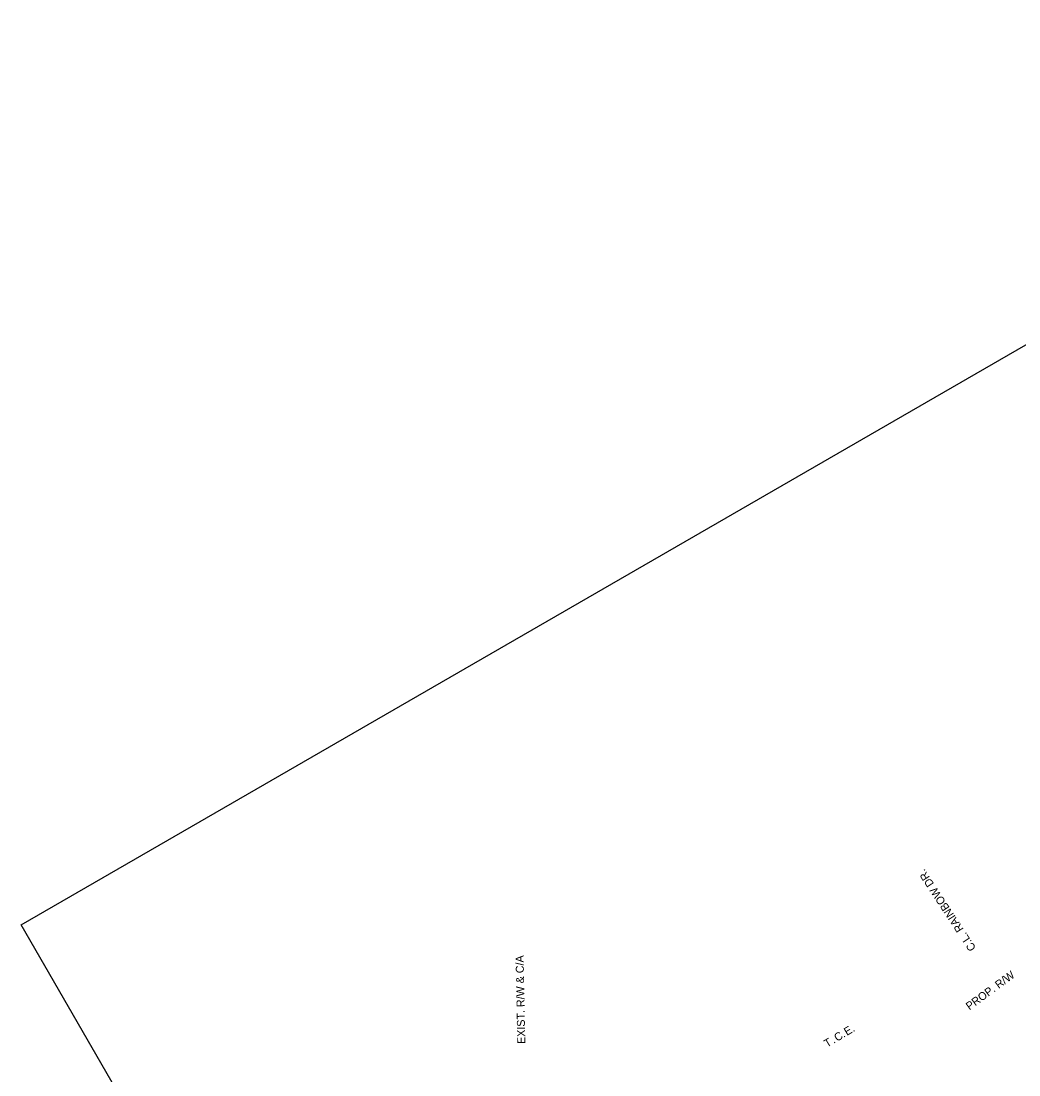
# Model space of a CAD drawing. Extents: x 1293524 to 1295623, y 222963 to 224839.
# Drawn here: x 1293524 to 1294272, y 223753 to 224543 of the extents above; entities that cross this region are included whole.
import ezdxf

# ---------------------------------------------------------------- set-up
doc = ezdxf.new("R2010")
doc.units = 0
for name, color, linetype in [('10Tan10', 7, 'Continuous'), ('Default', 7, 'Continuous'), ('G-No Plot-Border-1', 7, 'Continuous'), ('R_Draft', 7, 'Continuous')]:
    doc.layers.add(name, color=color, linetype=linetype)

msp = doc.modelspace()

# ---------------------------------------------------------------- linework, layer by layer
at = {"layer": 'G-No Plot-Border-1'}
msp.add_lwpolyline([(1294045.04, 222962.86), (1293523.88, 223865.53), (1294561.39, 224464.54), (1294586.16, 224421.63), (1294757.85, 224520.75), (1294765.6, 224507.33), (1294827.61, 224543.13), (1294901.36, 224415.39), (1295011.78, 224479.14), (1295426.66, 223760.54)], close=True, dxfattribs=at)
msp.add_lwpolyline([(1294045.04, 222962.86), (1293523.88, 223865.53), (1294561.39, 224464.54), (1294586.16, 224421.63), (1294757.85, 224520.75), (1294765.6, 224507.33), (1294827.61, 224543.13), (1294901.36, 224415.39), (1295011.78, 224479.14), (1295426.66, 223760.54)], close=True, dxfattribs=at)
msp.add_lwpolyline([(1294045.04, 222962.86), (1293523.88, 223865.53), (1294561.39, 224464.54), (1294586.16, 224421.63), (1294757.85, 224520.75), (1294765.6, 224507.33), (1294827.61, 224543.13), (1294901.36, 224415.39), (1295011.78, 224479.14), (1295426.66, 223760.54)], close=True, dxfattribs=at)
msp.add_lwpolyline([(1294045.04, 222962.86), (1293523.88, 223865.53), (1294561.39, 224464.54), (1294586.16, 224421.63), (1294757.85, 224520.75), (1294765.6, 224507.33), (1294827.61, 224543.13), (1294901.36, 224415.39), (1295011.78, 224479.14), (1295426.66, 223760.54)], close=True, dxfattribs=at)

# ---------------------------------------------------------------- texts
at = {"layer": '10Tan10'}
for s, rotation, p in [('EXIST. R/W & C/A', 91.19347, (1293901.92, 223776.28)), ('PROP. R/W', 36.33859, (1294234.88, 223801.25))]:
    msp.add_text(s, height=6, rotation=rotation, dxfattribs=at).set_placement(p)
at = {"layer": 'Default'}
msp.add_text('C.L. RAINBOW DR.', height=6, rotation=123.2, dxfattribs=at).set_placement((1294240, 223848.18))
at = {"layer": 'R_Draft'}
for s, p in [('C', (1294135.62, 223777.82)), ('E', (1294142.99, 223782.24)), ('.', (1294147.61, 223785.01)), ('T', (1294128.08, 223773.3)), ('.', (1294133.1, 223776.32)), ('.', (1294140.48, 223780.74))]:
    msp.add_text(s, height=6, rotation=30.9348, dxfattribs=at).set_placement(p)

doc.saveas('drawing.dxf')
